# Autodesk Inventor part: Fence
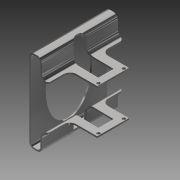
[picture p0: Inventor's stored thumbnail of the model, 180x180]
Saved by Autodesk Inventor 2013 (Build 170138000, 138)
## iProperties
Created: 2008-06
Part Number: Fence
Document SubType Name: Sheet Metal
Designer: tangg
Density: 7.84 g/cm^3
Mass: 20.0562 g
Surface Area: 218.78 cm^2
Volume: 20.0562 cm^3
Stock Number: Fence
Material: Steel, High Strength Low Alloy
Sheet Metal Rule: Default
Author: tangg
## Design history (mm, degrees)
node "Contour Flange1"
  sketch "Sketch1"
    geometry: L1 (-61.625, 21)-(-88.625, 21); L2 (-96.125, 28.5)-(-96.125, 36.825); L3 (-99.3, 40)-(-102.475, 40); L4 (-105.65, 36.825)-(-105.65, -36.825); L5 (-102.475, -40)-(-99.3, -40); L6 (-96.125, -36.825)-(-96.125, -28.5); L7 (-88.625, -21)-(-61.625, -21); L8 (-88.625, 28.5)-(-88.625, -28.5); A1 r 7.5 centre (-88.625, 28.5) between (-96.125, 28.5) and (-88.625, 21); A2 r 7.5 centre (-88.625, -28.5) between (-88.625, -21) and (-96.125, -28.5); A3 r 3.175 centre (-102.475, 36.825) between (-102.475, 40) and (-105.65, 36.825); A4 r 3.175 centre (-99.3, 36.825) between (-96.125, 36.825) and (-99.3, 40); A5 r 3.175 centre (-102.475, -36.825) between (-105.65, -36.825) and (-102.475, -40); A6 r 3.175 centre (-99.3, -36.825) between (-99.3, -40) and (-96.125, -36.825); 3 further points
    constraints: 16 end point, 12 point on circle, 12 tangent, 6 centre point, 4 equal radius, 2 horizontal alignment, 2 midpoint, 2 perpendicular, 1 collinear, 1 horizontal, 1 parallel
    dimensions: "d0" = 3.175 radius of A3; "d21" = 42 distance between parallel lines of L7 L1; "d22" = 7.5 radius of A1; "d23" = 9.525 distance between parallel lines of L2 L4; "d24" = 7.5 radius of A2 (derived); "d25" = 27 distance of L7.start L7.end; "d26" = 80 distance between parallel lines of L5 L3
sketch "Sketch2"
  geometry: L1 (88.9, -38.1)-(88.9, -22.542); L2 (82.55, -16.192)-(53.975, -16.193); L3 (88.9, 21.908)-(88.9, 39.688); L4 (82.55, 15.558)-(53.975, 15.557); L5 (75.143, -0.318)-(295.098, -0.318); L6 (88.9, -38.1)-(53.975, -38.1); L7 (53.975, 39.688)-(88.9, 39.688); L8 (53.975, -38.1)-(53.975, -16.193); L9 (53.975, 15.557)-(53.975, 39.688); L10 (68.458, 7.655)-(90.487, 7.275); L11 (90.487, 7.275)-(90.487, -7.91); L12 (90.487, -7.91)-(68.458, -7.53); L13 (68.458, -7.53)-(68.458, 7.655); A1 r 6.35 centre (82.55, -22.542) between (88.9, -22.542) and (82.55, -16.192); A2 r 6.35 centre (82.55, 21.907) between (82.55, 15.558) and (88.9, 21.908); 2 further points; 1 other entity
  constraints: 26 end point, 4 point on circle, 4 tangent, 2 centre point, 2 parallel, 1 equal radius, 1 midpoint, 1 point on line, 1 vertical alignment, 2 other
  dimensions: "d11" = 15.875 distance between parallel lines of L5 L2; "d12" = 15.875 distance between parallel lines of L5 L4; "d13" = 6.35 radius of A1
extrude "Extrusion1" cut sketch "Sketch2" stored distance "d14" = 152.4; taper "d15" = 0 deg
sketch "Sketch3"
  geometry: L1 (-76.2, 73.65)-(-76.2, 0) reference; L2 (0, 0)-(0, 73.65) reference; L3 (-76.2, 73.65)-(0, 73.65) reference; L4 (-76.2, 0)-(0, 0) reference; L5 (-76.2, 36.825)-(0, 36.825); L6 (-38.1, 73.65)-(-38.1, 0); 2 further points; 1 other entity
  constraints: 5 midpoint, 4 end point, 2 other
cut "Cut1" sketch "Sketch3" dims "d16" = 1.5875 (= Thickness), "d17" = 0
fillet "Fillet1" dims "d18" = 3.175
sketch "Sketch4"
  geometry: C1 r 1.588 at (19.05, 3.175); C2 r 1.588 at (19.05, 28.575); 1 further point
  constraints: 2 centre point
extrude "Extrusion2" cut sketch "Sketch4" stored distance "d19" = 25.4; taper "d20" = 0 deg
body "Solid1"
face "Plate1" dims "d1" = 1.5875 (= BendReliefWidth), "d2" = 0.79375 (= BendReliefDepth), "d3" = 3.175 (= MinimumRemnant), "d4" = 1.5875 (= BendRadius), "d5" = 76.2, "d6" = 1.5875 (= BendRadius), "d7" = 3.048, "d8" = 6.35 (= CornerReliefSize), "d9" = 1.5875 (= Thickness), "d10" = 1.5875 (= JacobiRadiusSize), "SeamGap" = 0.00508, "Thickness" = 1.5875
bend "Bend1" dims "d1" = 1.5875 (= BendReliefWidth), "d2" = 0.79375 (= BendReliefDepth), "d3" = 3.175 (= MinimumRemnant), "d4" = 1.5875 (= BendRadius), "d6" = 1.5875 (= BendRadius), "d7" = 3.048, "SeamGap" = 0.00508, "Thickness" = 1.5875
feature "Corner1" dims "d7" = 3.048, "d8" = 6.35 (= CornerReliefSize), "d9" = 1.5875 (= Thickness), "d10" = 1.5875 (= JacobiRadiusSize)
other parameters: "KFactor" = 4.4, "BendRadius" = 1.5875 (= Thickness), "BendReliefWidth" = 1.5875 (= Thickness), "BendReliefDepth" = 0.79375 (= 0.5 x Thickness), "CornerReliefSize" = 6.35 (= 4 x Thickness), "MinimumRemnant" = 3.175 (= 2 x Thickness), "TransitionRadius" = 1.5875 (= BendRadius), "JacobiRadiusSize" = 1.5875 (= Thickness), "GapSize" = 1.5875 (= Thickness)
